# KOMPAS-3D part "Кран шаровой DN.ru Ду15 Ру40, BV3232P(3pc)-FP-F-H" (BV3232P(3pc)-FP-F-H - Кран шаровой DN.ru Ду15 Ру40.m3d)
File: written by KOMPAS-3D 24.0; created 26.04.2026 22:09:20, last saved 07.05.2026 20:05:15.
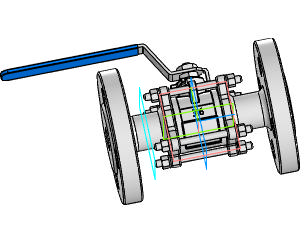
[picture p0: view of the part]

Document properties: Автор: Максим; Полное имя файла: BVxxP(3pc)-FP-F-H - Кран шаровой DN.ru Ду15 Ру40.cdw

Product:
- Body: Тело 1  | qty 1
    Масса: 2.156279
- Part/product: Кран шаровой DN.ru Ду15 Ру40  | designation BV3232P(3pc)-FP-F-H
    Масса: 1.985
    Раздел спецификации: Прочие изделия
    Форматы листов документа: A3
    Примечание: D160-22801

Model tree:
1. Операция без истории:1
2. Эскиз:1  (with: Ребро.Операция без истории:1)
3. Эскиз:6  (with: Грань.Операция без истории:1)
4. Элемент выдавливания:13
     Расстояние 2 = 16
5. Элемент выдавливания:14
     Расстояние 1 = 5
6. Эскиз:7  (with: Ребро.Элемент выдавливания:14)
7. Элемент выдавливания:15
     Расстояние 1 = 15
8. Эскиз:8  (with: Грань.Элемент выдавливания:14)
9. Элемент выдавливания:16
     Расстояние 1 = 6
10. Фаска:1  (with: Ребро.Элемент выдавливания:16)
     Угол = 45; Длина 1 = 1; Длина 2 = 1
11. Фаска:2  (with: Ребро.Элемент выдавливания:15)
     Угол = 45; Длина 1 = 4; Длина 2 = 4
12. Скругление:3  (with: Ребро.Элемент выдавливания:14)
     Радиус = 1
13. Скругление:4  (with: Ребро.Элемент выдавливания:14)
     Радиус = 3
14. Эскиз:9  (with: Ребро.Элемент выдавливания:15)
15. Элемент выдавливания:17
     Расстояние 1 = 16
16. Скругление:5  (with: Ребро.Элемент выдавливания:17)
     Радиус = 5
17. Скругление:6  (with: Ребро.Элемент выдавливания:17)
     Радиус = 0.5
18. Смещенная плоскость:1
     Расстояние = -37
19. Эскиз:10  (with: Грань.Операция без истории:1, Ребро.Операция без истории:1)
20. Элемент выдавливания:18
     Расстояние 2 = 141
21. Эскиз:11  (with: Грань.Элемент выдавливания:13)
22. Элемент выдавливания:19  (with: Грань.Операция без истории:1)
     Расстояние 1 = 13.75
23. Эскиз:12  (with: Грань.Операция без истории:1)
24. Элемент выдавливания:20
     Расстояние 1 = 2
25. Фаска:3  (with: Ребро.Элемент выдавливания:20)
     Угол = 45; Длина 1 = 1; Длина 2 = 1
26. Эскиз:13  (with: Ребро.Операция без истории:1)
27. Элемент выдавливания:21
     Расстояние 1 = 7; Расстояние 2 = 5
28. Зеркальный массив:1
29. Экземпляр ( 1 )
30. Экземпляр ( 2 )  (with: Элемент выдавливания:21)
31. Эскиз:14  (with: Грань.Операция без истории:1)
32. Элемент выдавливания:22
     Расстояние 2 = -2
33. Эскиз:15  (with: Грань.Операция без истории:1)
34. Элемент выдавливания:23
     Расстояние 1 = 0.2
35. Эскиз:16  (with: Грань.Операция без истории:1)
36. Элемент выдавливания:24
     Расстояние 1 = 0.2
37. Эскиз:17  (with: Грань.Элемент выдавливания:17, Ребро.Элемент выдавливания:17, Ребро.Скругление:6)
38. Элемент выдавливания:25
     Расстояние 2 = 0.2
39. Эскиз:19  (with: Грань.Операция без истории:1)
40. Элемент выдавливания:26
     Расстояние 2 = -9
41. Зеркальный массив:2  (with: Экземпляр ( 1 ), Экземпляр ( 2 ), Элемент выдавливания:26)
42. Эскиз:20  (with: Грань.Операция без истории:1, Ребро.Элемент выдавливания:26)
43. Элемент выдавливания:27
     Расстояние 1 = 2
44. Зеркальный массив:3  (with: Экземпляр ( 1 ), Экземпляр ( 2 ), Элемент выдавливания:27)
45. Эскиз:21  (with: Грань.Элемент выдавливания:27, Ребро.Операция без истории:1)
46. Элемент вращения:1
     Угол 1 = 360
47. Зеркальный массив:4  (with: Экземпляр ( 1 ), Экземпляр ( 2 ), Элемент вращения:1)

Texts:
  Точка начала. Х
  Точка начала. Y
  Точка начала. Z
  BV3232P(3pc)-FP-F-H
  DN15 PN40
